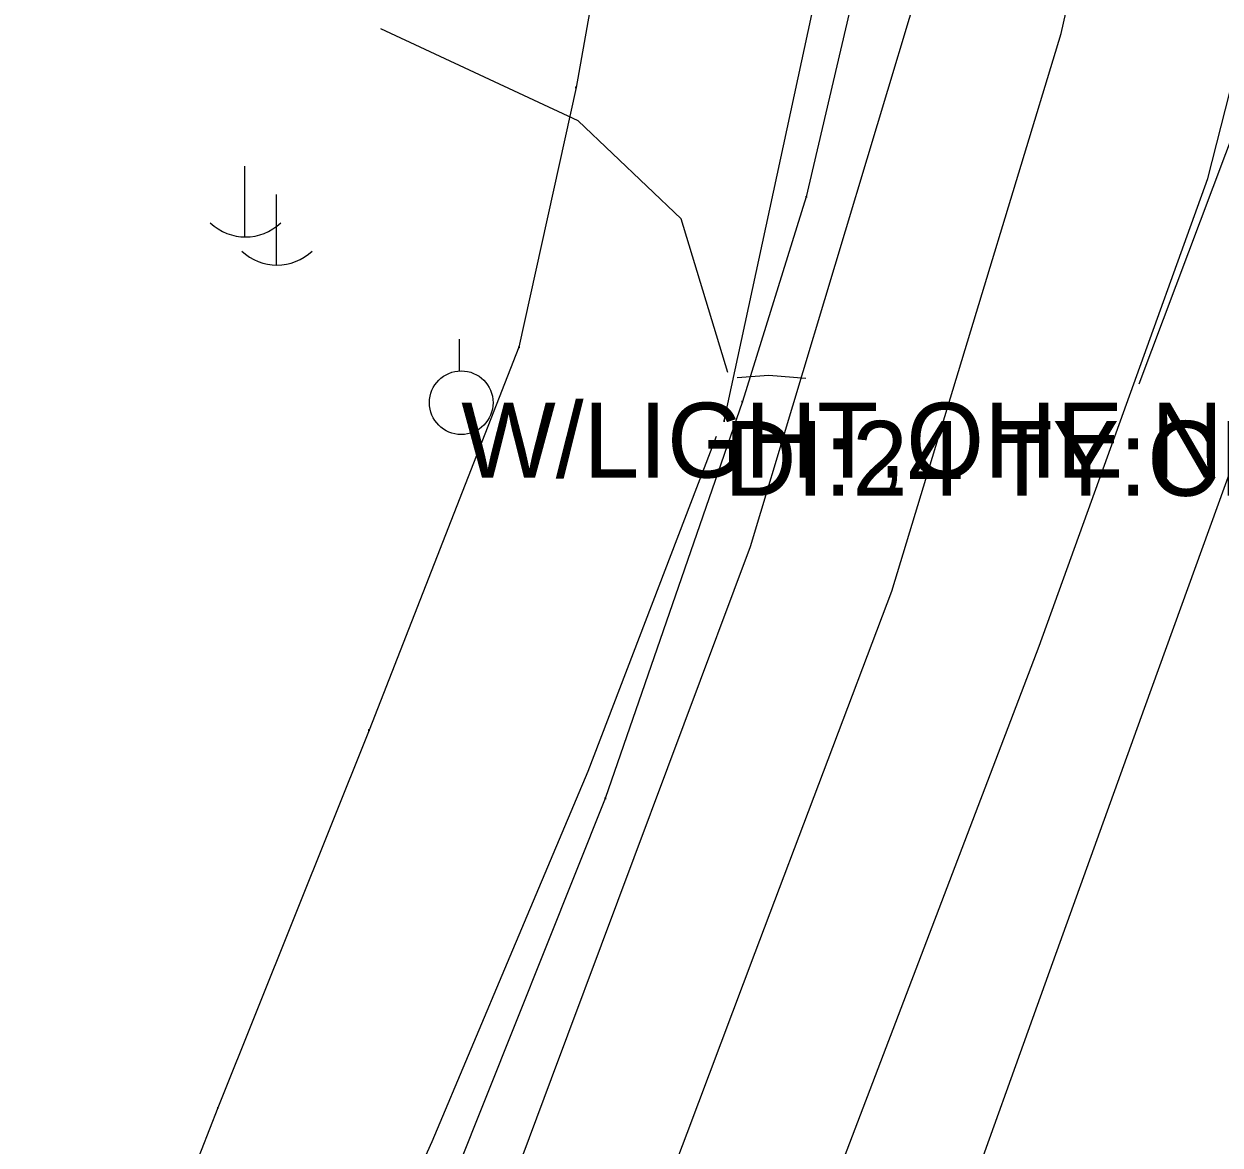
# Model space of a CAD drawing. Extents: x 997398 to 1003416, y 334596 to 337085.
# Drawn here: x 999523.3 to 999603.2, y 336342 to 336416.9 of the extents above; entities that cross this region are included whole.
import ezdxf

# ---------------------------------------------------------------- set-up
doc = ezdxf.new("R2010")
doc.units = 0
for name, color, linetype in [('S_CURB', 7, 'Continuous'), ('S_DITCHLINE', 7, 'Continuous'), ('S_DRG_PT_SYM', 7, 'Continuous'), ('S_EDGE_CONCRETE', 7, 'Continuous'), ('S_EDGE_PAVEMENT', 7, 'Continuous'), ('S_FIBER_OPTIC_CABLE', 7, 'Continuous'), ('S_GAS_UTILITIES', 7, 'Continuous'), ('S_PAVEMENT_CROWN', 7, 'Continuous'), ('S_SHOULDER', 7, 'Continuous'), ('S_SIDE_DRAIN', 7, 'Continuous'), ('S_SIDE_DRAIN_ANNOT', 7, 'Continuous'), ('S_UTILITY_POLE', 7, 'Continuous'), ('S_UTILITY_POLE_ANNOT', 7, 'Continuous'), ('S_UTL_PT_SYM', 7, 'Continuous')]:
    doc.layers.add(name, color=color, linetype=linetype)

msp = doc.modelspace()

# ---------------------------------------------------------------- linework, layer by layer
at = {"layer": 'S_CURB'}
msp.add_lwpolyline([(999570.357, 336393.637), (999567.248, 336403.911), (999560.372, 336410.45), (999547.179, 336416.598)], dxfattribs=at)
at = {"layer": 'S_DITCHLINE'}
for points in [[(999585.559, 336336.147), (999591.873, 336353.689), (999598.187, 336371.23), (999604.529, 336388.734), (999609.685, 336403.371), (999615.749, 336417.565), (999621.813, 336431.759), (999624.655, 336451.178), (999627.498, 336470.596), (999628.274, 336483.983), (999629.051, 336497.37), (999629.828, 336510.757), (999630.604, 336524.144), (999632.805, 336533.428), (999642.821, 336543.035), (999654.223, 336545.64), (999667.317, 336539.635), (999680.411, 336533.629)], [(999569.583, 336389.362), (999561.001, 336367.006), (999555.792, 336354.638), (999550.583, 336342.269), (999544.693, 336329.197), (999538.804, 336316.125), (999536.535, 336311.974)]]:
    msp.add_lwpolyline(points, dxfattribs=at)
at = {"layer": 'S_DRG_PT_SYM'}
msp.add_lwpolyline([(999570.119, 336390.407), (999570.119, 336390.457), (999570.119, 336390.407), (999570.069, 336390.407), (999570.119, 336390.407), (999570.119, 336390.357), (999570.119, 336390.407), (999570.169, 336390.407)], dxfattribs=at)
at = {"layer": 'S_EDGE_CONCRETE'}
msp.add_lwpolyline([(999575.566, 336393.247), (999573.101, 336393.436), (999570.975, 336393.295)], dxfattribs=at)
at = {"layer": 'S_EDGE_PAVEMENT'}
for points in [[(999554.17, 336334.665), (999558.594, 336346.502), (999563.018, 336358.339), (999567.442, 336370.176), (999571.867, 336382.013), (999577.521, 336400.817), (999583.175, 336419.622), (999585.747, 336433.436), (999588.319, 336447.251)], [(999577.333, 336339.095), (999581.942, 336351.182), (999586.55, 336363.27), (999591.159, 336375.357), (999596.786, 336390.98), (999602.412, 336406.602), (999606.841, 336423.998), (999611.269, 336441.394)]]:
    msp.add_lwpolyline(points, dxfattribs=at)
at = {"layer": 'S_FIBER_OPTIC_CABLE'}
for p, q in [((999565.702, 336443.165), (999560.22, 336412.681)), ((999560.22, 336412.681), (999556.41, 336395.323)), ((999556.41, 336395.323), (999546.398, 336369.767)), ((999546.398, 336369.767), (999536.302, 336344.534)), ((999536.302, 336344.534), (999523.349, 336311.497))]:
    msp.add_line(p, q, dxfattribs=at)
at = {"layer": 'S_GAS_UTILITIES'}
for p, q in [((999583.541, 336439.505), (999575.599, 336405.372)), ((999575.599, 336405.372), (999571.33, 336391.708)), ((999571.33, 336391.708), (999562.176, 336365.201)), ((999562.176, 336365.201), (999551.692, 336338.958))]:
    msp.add_line(p, q, dxfattribs=at)
at = {"layer": 'S_PAVEMENT_CROWN'}
msp.add_lwpolyline([(999563.08, 336330.783), (999567.638, 336342.849), (999572.195, 336354.915), (999576.753, 336366.981), (999581.31, 336379.047), (999586.968, 336397.667), (999592.627, 336416.287), (999595.959, 336431.091), (999599.292, 336445.895)], dxfattribs=at)
at = {"layer": 'S_SHOULDER'}
msp.add_lwpolyline([(999597.83, 336392.879), (999602.769, 336406.028), (999607.709, 336419.176), (999612.428, 336427.01), (999617.851, 336448.448), (999619.831, 336466.34), (999621.812, 336484.231), (999623.462, 336504.236), (999625.112, 336524.241), (999633.963, 336546.844), (999642.15, 336553.193), (999666.917, 336556.508), (999675.988, 336553.513), (999690.304, 336546.169), (999704.62, 336538.825), (999719.32, 336531.308), (999734.021, 336523.791)], dxfattribs=at)
at = {"layer": 'S_SIDE_DRAIN'}
msp.add_line((999570.119, 336390.407), (999582.785, 336449.278), dxfattribs=at)
at = {"layer": 'S_UTILITY_POLE'}
for p, q in [((999538.089, 336407.41), (999538.089, 336402.683)), ((999540.187, 336405.528), (999540.187, 336400.801)), ((999552.434, 336393.767), (999552.434, 336395.875))]:
    msp.add_line(p, q, dxfattribs=at)
msp.add_circle((999552.556, 336391.625), 2.127, dxfattribs=at)
for centre in [(999538.151, 336406.108), (999540.249, 336404.226)]:
    msp.add_arc(centre, 3.413, 226.39718, 313.60282, dxfattribs=at)
at = {"layer": 'S_UTL_PT_SYM'}
for points in [[(999560.22, 336412.681), (999560.22, 336412.731), (999560.22, 336412.681), (999560.17, 336412.681), (999560.22, 336412.681), (999560.22, 336412.631), (999560.22, 336412.681), (999560.27, 336412.681)], [(999575.599, 336405.372), (999575.599, 336405.422), (999575.599, 336405.372), (999575.549, 336405.372), (999575.599, 336405.372), (999575.599, 336405.322), (999575.599, 336405.372), (999575.649, 336405.372)], [(999556.41, 336395.323), (999556.41, 336395.373), (999556.41, 336395.323), (999556.361, 336395.323), (999556.41, 336395.323), (999556.41, 336395.273), (999556.41, 336395.323), (999556.461, 336395.323)], [(999571.33, 336391.708), (999571.33, 336391.758), (999571.33, 336391.708), (999571.28, 336391.708), (999571.33, 336391.708), (999571.33, 336391.658), (999571.33, 336391.708), (999571.38, 336391.708)], [(999546.398, 336369.767), (999546.398, 336369.817), (999546.398, 336369.767), (999546.348, 336369.767), (999546.398, 336369.767), (999546.398, 336369.717), (999546.398, 336369.767), (999546.448, 336369.767)], [(999562.176, 336365.201), (999562.176, 336365.251), (999562.176, 336365.201), (999562.126, 336365.201), (999562.176, 336365.201), (999562.176, 336365.151), (999562.176, 336365.201), (999562.226, 336365.201)], [(999536.302, 336344.534), (999536.302, 336344.584), (999536.302, 336344.534), (999536.252, 336344.534), (999536.302, 336344.534), (999536.302, 336344.484), (999536.302, 336344.534), (999536.352, 336344.534)]]:
    msp.add_lwpolyline(points, dxfattribs=at)

# ---------------------------------------------------------------- texts
at = {"layer": 'S_SIDE_DRAIN_ANNOT'}
msp.add_text('DI:24 TY:CMP CN:70% FILL', height=5, dxfattribs=at).set_placement((999570.119, 336385.407))
at = {"layer": 'S_UTILITY_POLE_ANNOT'}
msp.add_text('W/LIGHT,OHE NNE,SSW', height=5, dxfattribs=at).set_placement((999552.556, 336386.625))

doc.saveas('drawing.dxf')
